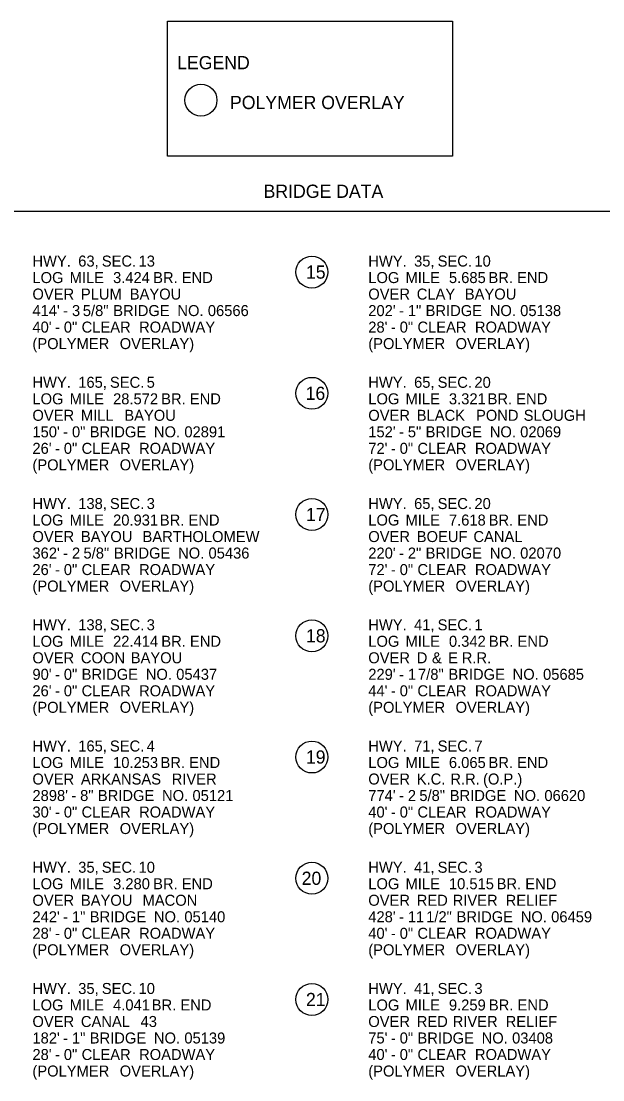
# Model space of a CAD drawing. Extents: x 1930546 to 1934225, y 596452 to 599536.
# Drawn here: x 1931071 to 1931599, y 598574 to 599536 of the extents above; entities that cross this region are included whole.
import ezdxf

# ---------------------------------------------------------------- set-up
doc = ezdxf.new("R2010")
doc.units = 0
doc.layers.add('Default', color=7, linetype='Continuous')
doc.layers.add('R_Border', color=7, linetype='Continuous')

msp = doc.modelspace()

# ---------------------------------------------------------------- linework, layer by layer
at = {"layer": 'R_Border'}
msp.add_line((1932141.6, 599363.54), (1930546.24, 599363.54), dxfattribs=at)
msp.add_lwpolyline([(1931203.83, 599536.42), (1931462.74, 599536.42), (1931462.74, 599413.76), (1931203.83, 599413.76)], close=True, dxfattribs=at)
for centre in [(1931234.29, 599464.65), (1931335.08, 599308.41), (1931335.08, 599198.23), (1931335.08, 599088.06), (1931335.08, 598977.88), (1931335.08, 598867.71), (1931335.08, 598757.53), (1931335.08, 598647.36)]:
    msp.add_circle(centre, 14.52, dxfattribs=at)

# ---------------------------------------------------------------- texts
at = {"layer": 'Default'}
for s, p in [('HWY.', (1931081.14, 599313.41)), (' 63,', (1931119.05, 599313.41)), (' SEC.', (1931140.46, 599313.41)), (' 13', (1931173.87, 599313.41)), ('HWY.', (1931386.32, 599313.41)), (' 35,', (1931424.22, 599313.41)), (' SEC.', (1931445.63, 599313.41)), (' 10', (1931479.04, 599313.41)), ('LOG', (1931081.14, 599298.41)), (' MILE', (1931111.27, 599298.41)), (' 3.424', (1931150.71, 599298.41)), (' BR.', (1931187.13, 599298.41)), (' END', (1931213.16, 599298.41)), ('LOG', (1931386.32, 599298.41)), (' MILE', (1931416.44, 599298.41)), (' 5.685', (1931455.89, 599298.41)), (' BR.', (1931491.84, 599298.41)), (' END', (1931517.87, 599298.41)), ('OVER', (1931081.14, 599283.41)), (' PLUM', (1931121.47, 599283.41)), (' BAYOU', (1931165.87, 599283.41)), ('OVER', (1931386.32, 599283.41)), (' CLAY', (1931426.64, 599283.41)), (' BAYOU', (1931470.32, 599283.41)), ("414'", (1931081.14, 599268.41)), (' 3', (1931113.37, 599268.41)), (' 5/8"', (1931123.22, 599268.41)), (' BRIDGE', (1931150.85, 599268.41)), (' NO.', (1931209.16, 599268.41)), (' 06566', (1931236.82, 599268.41)), ("202'", (1931386.32, 599268.41)), (' 1"', (1931418.55, 599268.41)), (' BRIDGE', (1931434.68, 599268.41)), (' NO.', (1931492.99, 599268.41)), (' 05138', (1931520.65, 599268.41)), (' -', (1931105.34, 599268.41)), (' -', (1931410.52, 599268.41)), ("40'", (1931081.14, 599253.41)), (' -', (1931097.96, 599253.41)), (' 0"', (1931105.98, 599253.41)), (' CLEAR', (1931122.12, 599253.41)), (' ROADWAY', (1931174.34, 599253.41)), ("28'", (1931386.32, 599253.41)), (' -', (1931403.13, 599253.41)), (' 0"', (1931411.16, 599253.41)), (' CLEAR', (1931427.29, 599253.41)), (' ROADWAY', (1931479.51, 599253.41)), ('(POLYMER', (1931081.14, 599238.41)), (' OVERLAY)', (1931156.75, 599238.41)), ('(POLYMER', (1931386.32, 599238.41)), (' OVERLAY)', (1931461.92, 599238.41)), ('HWY.', (1931081.14, 599203.23)), (' 165,', (1931119.05, 599203.23)), (' SEC.', (1931147.84, 599203.23)), (' 5', (1931181.25, 599203.23)), ('HWY.', (1931386.32, 599203.23)), (' 65,', (1931424.22, 599203.23)), (' SEC.', (1931445.63, 599203.23)), (' 20', (1931479.04, 599203.23)), ('LOG', (1931081.14, 599188.23)), (' MILE', (1931111.27, 599188.23)), (' 28.572', (1931150.71, 599188.23)), (' BR.', (1931194.42, 599188.23)), (' END', (1931220.45, 599188.23)), ('LOG', (1931386.32, 599188.23)), (' MILE', (1931416.44, 599188.23)), (' 3.321', (1931455.89, 599188.23)), (' BR.', (1931491.01, 599188.23)), (' END', (1931517.04, 599188.23)), ('OVER', (1931081.14, 599173.23)), (' MILL', (1931121.47, 599173.23)), (' BAYOU', (1931160.93, 599173.23)), ('OVER', (1931386.32, 599173.23)), (' BLACK', (1931426.64, 599173.23)), (' POND', (1931480.5, 599173.23)), (' SLOUGH', (1931523.83, 599173.23)), ("150'", (1931081.14, 599158.23)), (' -', (1931105.34, 599158.23)), (' 0"', (1931113.37, 599158.23)), (' BRIDGE', (1931129.5, 599158.23)), (' NO.', (1931187.82, 599158.23)), (' 02891', (1931215.48, 599158.23)), ("152'", (1931386.32, 599158.23)), (' -', (1931410.52, 599158.23)), (' 5"', (1931418.55, 599158.23)), (' BRIDGE', (1931434.68, 599158.23)), (' NO.', (1931492.99, 599158.23)), (' 02069', (1931520.65, 599158.23)), ("26'", (1931081.14, 599143.23)), (' 0"', (1931105.98, 599143.23)), (' CLEAR', (1931122.12, 599143.23)), (' ROADWAY', (1931174.34, 599143.23)), ("72'", (1931386.32, 599143.23)), (' 0"', (1931411.16, 599143.23)), (' CLEAR', (1931427.29, 599143.23)), (' ROADWAY', (1931479.51, 599143.23)), (' -', (1931097.96, 599143.23)), (' -', (1931403.13, 599143.23)), ('(POLYMER', (1931081.14, 599128.23)), (' OVERLAY)', (1931156.75, 599128.23)), ('(POLYMER', (1931386.32, 599128.23)), (' OVERLAY)', (1931461.92, 599128.23)), ('HWY.', (1931081.14, 599093.06)), (' 138,', (1931119.05, 599093.06)), (' SEC.', (1931147.84, 599093.06)), (' 3', (1931181.25, 599093.06)), ('HWY.', (1931386.32, 599093.06)), (' 65,', (1931424.22, 599093.06)), (' SEC.', (1931445.63, 599093.06)), (' 20', (1931479.04, 599093.06)), ('LOG', (1931081.14, 599078.06)), (' MILE', (1931111.27, 599078.06)), (' 20.931', (1931150.71, 599078.06)), (' BR.', (1931193.22, 599078.06)), (' END', (1931219.25, 599078.06)), ('LOG', (1931386.32, 599078.06)), (' MILE', (1931416.44, 599078.06)), (' 7.618', (1931455.89, 599078.06)), (' BR.', (1931491.97, 599078.06)), (' END', (1931518, 599078.06)), ('OVER', (1931081.14, 599063.06)), (' BAYOU', (1931121.47, 599063.06)), (' BARTHOLOMEW', (1931177.49, 599063.06)), ('OVER', (1931386.32, 599063.06)), (' BOEUF', (1931426.64, 599063.06)), (' CANAL', (1931478.13, 599063.06)), ("362'", (1931081.14, 599048.06)), (' 2', (1931113.37, 599048.06)), (' 5/8"', (1931123.83, 599048.06)), (' BRIDGE', (1931151.46, 599048.06)), (' NO.', (1931209.78, 599048.06)), (' 05436', (1931237.44, 599048.06)), ("220'", (1931386.32, 599048.06)), (' 2"', (1931418.55, 599048.06)), (' BRIDGE', (1931434.68, 599048.06)), (' NO.', (1931492.99, 599048.06)), (' 02070', (1931520.65, 599048.06)), (' -', (1931105.34, 599048.06)), (' -', (1931410.52, 599048.06)), ("26'", (1931081.14, 599033.06)), (' -', (1931097.96, 599033.06)), (' 0"', (1931105.98, 599033.06)), (' CLEAR', (1931122.12, 599033.06)), (' ROADWAY', (1931174.34, 599033.06)), ("72'", (1931386.32, 599033.06)), (' -', (1931403.13, 599033.06)), (' 0"', (1931411.16, 599033.06)), (' CLEAR', (1931427.29, 599033.06)), (' ROADWAY', (1931479.51, 599033.06)), ('(POLYMER', (1931081.14, 599018.06)), (' OVERLAY)', (1931156.75, 599018.06)), ('(POLYMER', (1931386.32, 599018.06)), (' OVERLAY)', (1931461.92, 599018.06)), ('HWY.', (1931081.14, 598982.88)), (' 138,', (1931119.05, 598982.88)), (' SEC.', (1931147.84, 598982.88)), (' 3', (1931181.25, 598982.88)), ('HWY.', (1931386.32, 598982.88)), (' 41,', (1931424.22, 598982.88)), (' SEC.', (1931445.63, 598982.88)), (' 1', (1931479.04, 598982.88)), ('LOG', (1931081.14, 598967.88)), (' MILE', (1931111.27, 598967.88)), (' 22.414', (1931150.71, 598967.88)), (' BR.', (1931194.52, 598967.88)), (' END', (1931220.55, 598967.88)), ('LOG', (1931386.32, 598967.88)), (' MILE', (1931416.44, 598967.88)), (' 0.342', (1931455.89, 598967.88)), (' BR.', (1931492.2, 598967.88)), (' END', (1931518.23, 598967.88)), ('OVER', (1931081.14, 598952.88)), (' COON', (1931121.47, 598952.88)), (' BAYOU', (1931166.78, 598952.88)), ('OVER', (1931386.32, 598952.88)), (' D', (1931426.64, 598952.88)), (' &', (1931440.44, 598952.88)), (' E', (1931455.17, 598952.88)), (' R.R.', (1931467.55, 598952.88)), ("90'", (1931081.14, 598937.88)), (' -', (1931097.96, 598937.88)), (' 0"', (1931105.98, 598937.88)), (' BRIDGE', (1931122.12, 598937.88)), (' NO.', (1931180.43, 598937.88)), (' 05437', (1931208.09, 598937.88)), ("229'", (1931386.32, 598937.88)), (' -', (1931410.52, 598937.88)), (' 1', (1931418.55, 598937.88)), (' 7/8"', (1931427.81, 598937.88)), (' BRIDGE', (1931455.44, 598937.88)), (' NO.', (1931513.75, 598937.88)), (' 05685', (1931541.41, 598937.88)), ("26'", (1931081.14, 598922.88)), (' 0"', (1931105.98, 598922.88)), (' CLEAR', (1931122.12, 598922.88)), (' ROADWAY', (1931174.34, 598922.88)), ("44'", (1931386.32, 598922.88)), (' 0"', (1931411.16, 598922.88)), (' CLEAR', (1931427.29, 598922.88)), (' ROADWAY', (1931479.51, 598922.88)), (' -', (1931097.96, 598922.88)), (' -', (1931403.13, 598922.88)), ('(POLYMER', (1931081.14, 598907.88)), (' OVERLAY)', (1931156.75, 598907.88)), ('(POLYMER', (1931386.32, 598907.88)), (' OVERLAY)', (1931461.92, 598907.88)), ('HWY.', (1931081.14, 598872.71)), (' 165,', (1931119.05, 598872.71)), (' SEC.', (1931147.84, 598872.71)), (' 4', (1931181.25, 598872.71)), ('HWY.', (1931386.32, 598872.71)), (' 71,', (1931424.22, 598872.71)), (' SEC.', (1931445.63, 598872.71)), (' 7', (1931479.04, 598872.71)), ('LOG', (1931081.14, 598857.71)), (' MILE', (1931111.27, 598857.71)), (' 10.253', (1931150.71, 598857.71)), (' BR.', (1931193.8, 598857.71)), (' END', (1931219.83, 598857.71)), ('LOG', (1931386.32, 598857.71)), (' MILE', (1931416.44, 598857.71)), (' 6.065', (1931455.89, 598857.71)), (' BR.', (1931491.84, 598857.71)), (' END', (1931517.87, 598857.71)), ('OVER', (1931081.14, 598842.71)), (' ARKANSAS', (1931121.47, 598842.71)), (' RIVER', (1931203.97, 598842.71)), ('OVER', (1931386.32, 598842.71)), (' K.C.', (1931426.64, 598842.71)), (' R.R.', (1931457.18, 598842.71)), (' (O.P.)', (1931486.9, 598842.71)), ("2898'", (1931081.14, 598827.71)), (' 8"', (1931120.76, 598827.71)), (' BRIDGE', (1931136.89, 598827.71)), (' NO.', (1931195.21, 598827.71)), (' 05121', (1931222.87, 598827.71)), ("774'", (1931386.32, 598827.71)), (' 2', (1931418.55, 598827.71)), (' 5/8"', (1931429.01, 598827.71)), (' BRIDGE', (1931456.64, 598827.71)), (' NO.', (1931514.95, 598827.71)), (' 06620', (1931542.61, 598827.71)), (' -', (1931112.73, 598827.71)), (' -', (1931410.52, 598827.71)), ("30'", (1931081.14, 598812.71)), (' -', (1931097.96, 598812.71)), (' 0"', (1931105.98, 598812.71)), (' CLEAR', (1931122.12, 598812.71)), (' ROADWAY', (1931174.34, 598812.71)), ("40'", (1931386.32, 598812.71)), (' -', (1931403.13, 598812.71)), (' 0"', (1931411.16, 598812.71)), (' CLEAR', (1931427.29, 598812.71)), (' ROADWAY', (1931479.51, 598812.71)), ('(POLYMER', (1931081.14, 598797.71)), (' OVERLAY)', (1931156.75, 598797.71)), ('(POLYMER', (1931386.32, 598797.71)), (' OVERLAY)', (1931461.92, 598797.71)), ('HWY.', (1931081.14, 598762.53)), (' 35,', (1931119.05, 598762.53)), (' SEC.', (1931140.46, 598762.53)), (' 10', (1931173.87, 598762.53)), ('HWY.', (1931386.32, 598762.53)), (' 41,', (1931424.22, 598762.53)), (' SEC.', (1931445.63, 598762.53)), (' 3', (1931479.04, 598762.53)), ('LOG', (1931081.14, 598747.53)), (' MILE', (1931111.27, 598747.53)), (' 3.280', (1931150.71, 598747.53)), (' BR.', (1931187.12, 598747.53)), (' END', (1931213.15, 598747.53)), ('LOG', (1931386.32, 598747.53)), (' MILE', (1931416.44, 598747.53)), (' 10.515', (1931455.89, 598747.53)), (' BR.', (1931499.23, 598747.53)), (' END', (1931525.26, 598747.53)), ('OVER', (1931081.14, 598732.53)), (' BAYOU', (1931121.47, 598732.53)), (' MACON', (1931177.49, 598732.53)), ('OVER', (1931386.32, 598732.53)), (' RED', (1931426.64, 598732.53)), (' RIVER', (1931459.3, 598732.53)), (' RELIEF', (1931507.43, 598732.53)), ("242'", (1931081.14, 598717.53)), (' 1"', (1931113.37, 598717.53)), (' BRIDGE', (1931129.5, 598717.53)), (' NO.', (1931187.82, 598717.53)), (' 05140', (1931215.48, 598717.53)), ("428'", (1931386.32, 598717.53)), (' 11', (1931418.55, 598717.53)), (' 1/2"', (1931435.2, 598717.53)), (' BRIDGE', (1931462.83, 598717.53)), (' NO.', (1931521.14, 598717.53)), (' 06459', (1931548.8, 598717.53)), (' -', (1931105.34, 598717.53)), (' -', (1931410.52, 598717.53)), ("28'", (1931081.14, 598702.53)), (' 0"', (1931105.98, 598702.53)), (' CLEAR', (1931122.12, 598702.53)), (' ROADWAY', (1931174.34, 598702.53)), ("40'", (1931386.32, 598702.53)), (' 0"', (1931411.16, 598702.53)), (' CLEAR', (1931427.29, 598702.53)), (' ROADWAY', (1931479.51, 598702.53)), (' -', (1931097.96, 598702.53)), (' -', (1931403.13, 598702.53)), ('(POLYMER', (1931081.14, 598687.53)), (' OVERLAY)', (1931156.75, 598687.53)), ('(POLYMER', (1931386.32, 598687.53)), (' OVERLAY)', (1931461.92, 598687.53)), ('HWY.', (1931081.14, 598652.36)), (' 35,', (1931119.05, 598652.36)), (' SEC.', (1931140.46, 598652.36)), (' 10', (1931173.87, 598652.36)), ('HWY.', (1931386.32, 598652.36)), (' 41,', (1931424.22, 598652.36)), (' SEC.', (1931445.63, 598652.36)), (' 3', (1931479.04, 598652.36)), ('LOG', (1931081.14, 598637.36)), (' MILE', (1931111.27, 598637.36)), (' 4.041', (1931150.71, 598637.36)), (' BR.', (1931185.83, 598637.36)), (' END', (1931211.86, 598637.36)), ('LOG', (1931386.32, 598637.36)), (' MILE', (1931416.44, 598637.36)), (' 9.259', (1931455.89, 598637.36)), (' BR.', (1931492.19, 598637.36)), (' END', (1931518.22, 598637.36)), ('OVER', (1931081.14, 598622.36)), (' CANAL', (1931121.47, 598622.36)), (' 43', (1931175.7, 598622.36)), ('OVER', (1931386.32, 598622.36)), (' RED', (1931426.64, 598622.36)), (' RIVER', (1931459.3, 598622.36)), (' RELIEF', (1931507.43, 598622.36)), ("182'", (1931081.14, 598607.36)), (' -', (1931105.34, 598607.36)), (' 1"', (1931113.37, 598607.36)), (' BRIDGE', (1931129.5, 598607.36)), (' NO.', (1931187.82, 598607.36)), (' 05139', (1931215.48, 598607.36)), ("75'", (1931386.32, 598607.36)), (' -', (1931403.13, 598607.36)), (' 0"', (1931411.16, 598607.36)), (' BRIDGE', (1931427.29, 598607.36)), (' NO.', (1931485.61, 598607.36)), (' 03408', (1931513.27, 598607.36)), ("28'", (1931081.14, 598592.36)), (' 0"', (1931105.98, 598592.36)), (' CLEAR', (1931122.12, 598592.36)), (' ROADWAY', (1931174.34, 598592.36)), ("40'", (1931386.32, 598592.36)), (' 0"', (1931411.16, 598592.36)), (' CLEAR', (1931427.29, 598592.36)), (' ROADWAY', (1931479.51, 598592.36)), (' -', (1931097.96, 598592.36)), (' -', (1931403.13, 598592.36)), ('(POLYMER', (1931081.14, 598577.36)), (' OVERLAY)', (1931156.75, 598577.36)), ('(POLYMER', (1931386.32, 598577.36)), (' OVERLAY)', (1931461.92, 598577.36))]:
    msp.add_text(s, height=10, rotation=360, dxfattribs=at).set_placement(p)
at = {"layer": 'R_Border'}
for s, p in [('LEGEND', (1931212.64, 599492.74)), ('POLYMER OVERLAY', (1931260.65, 599456.53)), ('BRIDGE DATA', (1931291.18, 599375.86)), ('15', (1931329.69, 599302.41)), ('16', (1931329.36, 599192.23)), ('17', (1931329.69, 599082.06)), ('18', (1931329.69, 598971.88)), ('19', (1931329.64, 598861.71)), ('20', (1931325.77, 598751.53)), ('21', (1931329.69, 598641.36))]:
    msp.add_text(s, height=12, rotation=360, dxfattribs=at).set_placement(p)

doc.saveas('drawing.dxf')
